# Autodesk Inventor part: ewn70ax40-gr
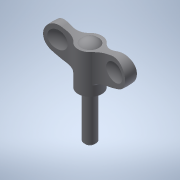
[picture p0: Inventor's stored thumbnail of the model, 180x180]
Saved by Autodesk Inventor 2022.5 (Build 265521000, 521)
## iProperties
Created: 2016-12
Part Number: ewn70ax40-gr
Material: 一般
Document SubType Name: Modeling
Designer: imaocorp
Density: 1 g/cm^3
Appearance: 既定
Author: imaocorp
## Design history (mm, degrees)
node "ewn70ax40-gr.x_t1"
node "ewn70ax40-gr"
node "Base1"
